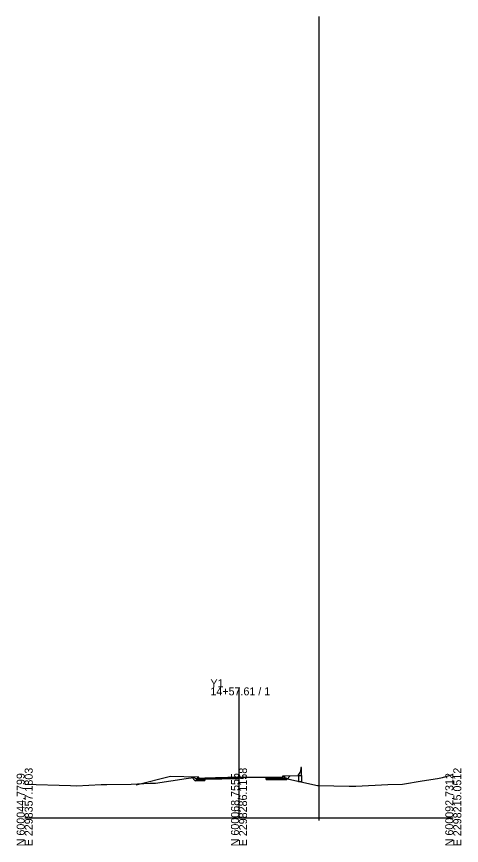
# Model space of a CAD drawing. Extents: x -26 to 2453, y -10 to 6530.
# Drawn here: x 1147.2 to 1302.8, y -9.7 to 280.3 of the extents above; entities that cross this region are included whole.
import ezdxf

# ---------------------------------------------------------------- set-up
doc = ezdxf.new("R2010")
doc.units = 0
for name, color, linetype in [('Default', 7, 'Continuous'), ('Exist CMT Pavement', 7, 'Continuous'), ('Exist Cross Section Cell', 7, 'Continuous'), ('Exist XS Center Line Elevation Label', 7, 'Continuous'), ('Exist XS Ground Line', 7, 'Continuous'), ('Prop CMT Conc Surface', 7, 'Continuous'), ('Prop CMT Concrete Structures', 7, 'Continuous'), ('Prop CMT Pvmt Course 1', 7, 'Continuous'), ('Prop CMT Pvmt Course 1 CG', 7, 'Continuous'), ('Prop CMT Pvmt Course 2', 7, 'Continuous'), ('Prop CMT Pvmt Course 3', 7, 'Continuous'), ('Prop CMT Pvmt Surface', 7, 'Continuous'), ('Prop CMT Pvmt Wedge Surface 1', 7, 'Continuous'), ('Prop CMT Pvmt Wedge Surface 2', 7, 'Continuous'), ('Prop CMT Pvmt Wedge Surface 3', 7, 'Continuous'), ('Prop CMT Slope Grass', 7, 'Continuous'), ('Prop CMT Subgrade Earthwork', 7, 'Continuous'), ('Prop XS Retaining Wall', 7, 'Continuous'), ('Scratch_Level_0', 7, 'Continuous'), ('Typical Median Barrier CELL', 7, 'Continuous')]:
    doc.layers.add(name, color=color, linetype=linetype)

msp = doc.modelspace()

# ---------------------------------------------------------------- linework, layer by layer
at = {"layer": 'Exist CMT Pavement'}
msp.add_lwpolyline([(1225, 14.06), (1213.01, 13.66)], dxfattribs=at)
at = {"layer": 'Exist Cross Section Cell'}
for p, q in [((1225, 0), (1225, 45.62)), ((1150, 0), (1225, 0)), ((1225, 0), (1300, 0))]:
    msp.add_line(p, q, dxfattribs=at)
at = {"layer": 'Exist XS Ground Line'}
msp.add_lwpolyline([(1150, 11.77), (1166.05, 11.24), (1168.18, 11.21), (1176.74, 11.6), (1178.69, 11.68), (1187.29, 11.74), (1193.86, 12.06), (1195.82, 12.13), (1206.47, 13.75), (1209.08, 14.12), (1209.97, 13.71), (1211.09, 13.71), (1211.83, 13.76), (1213.25, 13.84), (1215.62, 13.98), (1216.83, 14.02), (1218.26, 14.07), (1221.07, 14.12), (1222.92, 14.13), (1223.54, 14.13), (1224.41, 14.14), (1225.05, 14.17), (1225.44, 14.19), (1226.18, 14.21), (1228.89, 14.23), (1231.45, 14.24), (1232.76, 14.21), (1234.09, 14.2), (1234.75, 14.19), (1236.73, 14.14), (1237.65, 14.01), (1239.4, 13.87), (1240.34, 14.35), (1241.4, 13.96), (1242.45, 13.46), (1252.49, 11.3), (1252.82, 11.26), (1263.5, 11.02), (1264.06, 11.08), (1265.92, 11.08), (1277.05, 11.65), (1282.24, 11.72), (1289.12, 12.91), (1294.45, 13.73), (1296.18, 14.09), (1299.37, 15.06), (1300, 15.21)], dxfattribs=at)
at = {"layer": 'Prop CMT Conc Surface'}
for points in [[(1240.38, 14.14), (1240.37, 14.64), (1240.87, 14.65)], [(1211, 13.73), (1211, 14.23), (1210.5, 14.23)], [(1213, 13.86), (1211, 13.73)], [(1238.38, 14.21), (1240.38, 14.14)]]:
    msp.add_lwpolyline(points, dxfattribs=at)
at = {"layer": 'Prop CMT Concrete Structures'}
for points in [[(1238.38, 14.21), (1240.38, 14.14), (1240.37, 14.64), (1240.87, 14.65)], [(1240.87, 14.65), (1240.9, 13.64), (1238.4, 13.63)], [(1213, 13.86), (1211, 13.73), (1211, 14.23), (1210.5, 14.23)], [(1210.5, 14.23), (1210.5, 13.22), (1213, 13.28)], [(1213, 13.28), (1213, 13.86)], [(1238.4, 13.63), (1238.38, 14.21)]]:
    msp.add_lwpolyline(points, dxfattribs=at)
at = {"layer": 'Prop CMT Pvmt Course 1'}
for points in [[(1225, 14.16), (1213, 13.86)], [(1213, 13.86), (1213, 13.61)], [(1213, 13.61), (1213.01, 13.61)], [(1213.01, 13.74), (1225, 14.04)], [(1213.01, 13.61), (1213.01, 13.74)], [(1225, 14.16), (1238.38, 14.21)], [(1225, 13.91), (1225, 14.16)], [(1225, 13.91), (1225, 14.16)], [(1234.54, 14.07), (1225, 14.04)], [(1225, 14.04), (1225, 13.91), (1225, 13.91)], [(1225, 14.04), (1225, 13.91), (1225, 13.91)], [(1234.54, 13.95), (1234.54, 14.07)], [(1238.39, 13.96), (1234.54, 13.95)], [(1238.38, 14.21), (1238.39, 13.96)]]:
    msp.add_lwpolyline(points, dxfattribs=at)
at = {"layer": 'Prop CMT Pvmt Course 1 CG'}
for points in [[(1213, 13.28), (1210, 13.21), (1209.7, 12.91)], [(1209.7, 12.91), (1213, 12.99)], [(1213, 12.99), (1213, 13.28)], [(1238.4, 13.63), (1241.4, 13.64), (1241.71, 13.35)], [(1238.41, 13.34), (1238.4, 13.63)], [(1241.71, 13.35), (1238.41, 13.34)]]:
    msp.add_lwpolyline(points, dxfattribs=at)
at = {"layer": 'Prop CMT Pvmt Course 2'}
for points in [[(1213.01, 13.61), (1213, 13.61)], [(1213, 13.61), (1213, 13.36)], [(1213, 13.36), (1213.01, 13.36)], [(1213.01, 13.36), (1213.01, 13.61)], [(1234.54, 13.95), (1238.39, 13.96)], [(1234.55, 13.7), (1234.54, 13.95)], [(1238.4, 13.71), (1234.55, 13.7)], [(1238.39, 13.96), (1238.4, 13.71)]]:
    msp.add_lwpolyline(points, dxfattribs=at)
at = {"layer": 'Prop CMT Pvmt Course 3'}
for points in [[(1213.01, 13.36), (1213, 13.36)], [(1213, 13.36), (1213, 12.99)], [(1213, 12.99), (1213.01, 12.99)], [(1213.01, 12.99), (1213.01, 13.36)], [(1234.55, 13.7), (1238.4, 13.71)], [(1234.56, 13.32), (1234.55, 13.7)], [(1238.41, 13.34), (1234.56, 13.32)], [(1238.4, 13.71), (1238.41, 13.34)]]:
    msp.add_lwpolyline(points, dxfattribs=at)
at = {"layer": 'Prop CMT Pvmt Surface'}
for points in [[(1225, 14.16), (1213, 13.86)], [(1225, 14.16), (1238.38, 14.21)]]:
    msp.add_lwpolyline(points, dxfattribs=at)
at = {"layer": 'Prop CMT Pvmt Wedge Surface 1'}
for points in [[(1213, 13.61), (1213, 13.86)], [(1213.01, 13.61), (1213, 13.61)], [(1225, 14.04), (1213.01, 13.74)], [(1213.01, 13.74), (1213.01, 13.61)]]:
    msp.add_lwpolyline(points, dxfattribs=at)
at = {"layer": 'Prop CMT Pvmt Wedge Surface 2'}
for points in [[(1225, 13.91), (1213, 13.61)], [(1213, 13.61), (1213, 13.86)]]:
    msp.add_lwpolyline(points, dxfattribs=at)
at = {"layer": 'Prop CMT Pvmt Wedge Surface 3'}
for points in [[(1213, 13.36), (1213, 13.86)], [(1225, 13.66), (1213, 13.36)]]:
    msp.add_lwpolyline(points, dxfattribs=at)
at = {"layer": 'Prop CMT Slope Grass'}
for p, q in [((1240.87, 14.65), (1245.87, 14.75)), ((1245.87, 14.75), (1245.87, 12.51))]:
    msp.add_line(p, q, dxfattribs=at)
msp.add_lwpolyline([(1210.5, 14.23), (1201, 14.42), (1189.01, 11.43)], dxfattribs=at)
at = {"layer": 'Prop CMT Subgrade Earthwork'}
for points in [[(1238.41, 13.34), (1241.71, 13.35), (1242.95, 14.67)], [(1213, 12.99), (1209.7, 12.91), (1208.33, 14.28)], [(1213.01, 12.99), (1213, 12.99)], [(1213.01, 12.99), (1213.03, 13.66)], [(1234.56, 13.32), (1238.41, 13.34)]]:
    msp.add_lwpolyline(points, dxfattribs=at)
at = {"layer": 'Prop XS Retaining Wall'}
for p, q in [((1246.87, 14.75), (1246.87, 12.51)), ((1246.87, 12.51), (1245.87, 12.51))]:
    msp.add_line(p, q, dxfattribs=at)
at = {"layer": 'Scratch_Level_0'}
msp.add_line((1252.92, 280.31), (1252.92, -0.99), dxfattribs=at)
at = {"layer": 'Typical Median Barrier CELL'}
for p, q in [((1246.64, 17.59), (1246.48, 16.21)), ((1246.88, 17.59), (1246.64, 17.59)), ((1246.87, 14.75), (1246.88, 17.59)), ((1246.33, 15.83), (1245.87, 15.17)), ((1245.87, 14.75), (1245.87, 15.17)), ((1245.87, 14.75), (1246.87, 14.75))]:
    msp.add_line(p, q, dxfattribs=at)
msp.add_arc((1245.65, 16.31), 0.833, 325.0087, 353.179, dxfattribs=at)

# ---------------------------------------------------------------- texts
at = {"layer": 'Default'}
msp.add_text('-', height=0.0001, dxfattribs=at).set_placement((1150, 0))
at = {"layer": 'Exist Cross Section Cell'}
for s, p in [('Y1', (1215, 45.62)), ('14+57.61 / 1', (1215, 42.82))]:
    msp.add_text(s, height=2.8, dxfattribs=at).set_placement(p)
for s, p in [('N 600044.7799', (1150, -10)), ('E 2298357.1803', (1152.8, -10)), ('N 600068.7555', (1225, -10)), ('E 2298286.1158', (1227.8, -10)), ('N 600092.7312', (1300, -10)), ('E 2298215.0512', (1302.8, -10))]:
    msp.add_text(s, height=2.8, rotation=90, dxfattribs=at).set_placement(p)
at = {"layer": 'Exist XS Center Line Elevation Label'}
msp.add_text('119.16', height=1, dxfattribs=at).set_placement((1223.5, 13.66))

doc.saveas('drawing.dxf')
